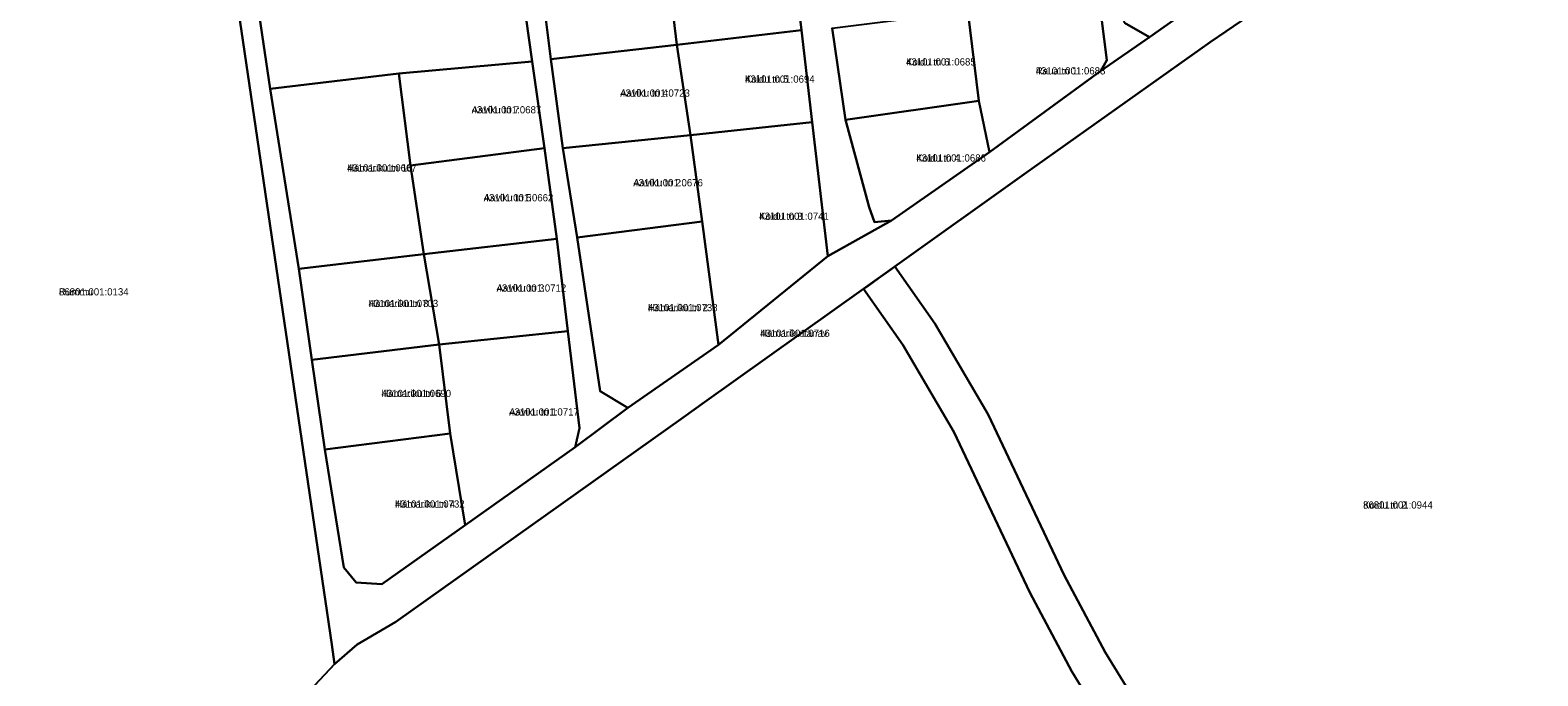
# Model space of a CAD drawing. Extents: x 484607 to 525396, y 6554521 to 6586559.
# Drawn here: x 510881.4 to 511195.3, y 6566189 to 6566323.4 of the extents above; entities that cross this region are included whole.
import ezdxf

# ---------------------------------------------------------------- set-up
doc = ezdxf.new("R2010")
doc.units = 0
for name, color, linetype in [('L_AADRESS', 7, 'Continuous'), ('PIIR', 7, 'Continuous'), ('TUNNUS', 7, 'Continuous')]:
    doc.layers.add(name, color=color, linetype=linetype)

msp = doc.modelspace()

# ---------------------------------------------------------------- linework, layer by layer
at = {"layer": 'PIIR'}
for points in [[(510798.29, 6566881.46), (510841.06, 6566895.36), (510898.65, 6566504.69), (510899.62, 6566498.05), (510944.17, 6566195.55), (510944.78, 6566191.44), (510919.04, 6566163.98), (510920.5, 6566161.21), (510972.39, 6566062.69), (510956.12, 6566056.16), (510964.27, 6566035.84), (510980.57, 6566010.49), (510903.8, 6565981.76), (510875.33, 6565935.94), (510855.65, 6566095.24), (510855.17, 6566099.11), (510854.85, 6566103.1), (510794.21, 6566862.32), (510794.75, 6566868.66)], [(511167.15, 6566348.39), (511195.72, 6566369.66), (511229.31, 6566328.43), (511197.85, 6566289.25), (511235.29, 6566228.71), (511213.97, 6566194.63), (511250.38, 6566142.85), (511256.39, 6566114.86), (511216.4, 6566103.03), (511185.24, 6566094.86), (511173.08, 6566091.4), (511165.87, 6566097.92), (511159.18, 6566104.64), (511153.91, 6566112.9), (511145.54, 6566128.22), (511105.24, 6566193.93), (511096.69, 6566209.97), (511080.89, 6566243.45), (511069.79, 6566262.38), (511061.46, 6566274.23), (511088.35, 6566293.42), (511127.12, 6566320.93), (511162.99, 6566345.41)], [(511109.24, 6566324.92), (511105.7, 6566349.28), (511132.11, 6566353.48), (511134.64, 6566336.25), (511114.47, 6566321.95)], [(510989.77, 6566317.4), (510987.42, 6566336.34), (511013.75, 6566339.47), (511016.02, 6566320.36)], [(511016.02, 6566320.36), (511013.75, 6566339.47), (511039.81, 6566341.91), (511041.99, 6566323.42)], [(510931.35, 6566311.19), (510928.61, 6566330.04), (510955.38, 6566333.19), (510983.27, 6566335.71), (510985.9, 6566316.93), (510958.13, 6566314.42)], [(511078.92, 6566308.7), (511076.65, 6566327.41), (511103.93, 6566330.36), (511105.55, 6566317.2), (511104.3, 6566314.95), (511081.13, 6566298.06)], [(511051.14, 6566304.74), (511048.39, 6566323.85), (511076.65, 6566327.41), (511078.92, 6566308.7)], [(511018.89, 6566301.56), (511016.02, 6566320.36), (511041.99, 6566323.42), (511044.21, 6566304.3)], [(510992.33, 6566298.83), (510989.77, 6566317.4), (511016.02, 6566320.36), (511018.89, 6566301.56)], [(510937.35, 6566273.71), (510931.35, 6566311.19), (510958.13, 6566314.42), (510960.55, 6566295.27), (510963.38, 6566276.77)], [(510960.55, 6566295.27), (510958.13, 6566314.42), (510985.9, 6566316.93), (510988.47, 6566298.84)], [(511056.11, 6566286.56), (511051.14, 6566304.74), (511078.92, 6566308.7), (511081.13, 6566298.06), (511060.76, 6566283.78), (511057.23, 6566283.44)], [(510995.3, 6566280.28), (510992.33, 6566298.83), (511018.89, 6566301.56), (511021.33, 6566283.6)], [(511021.33, 6566283.6), (511018.89, 6566301.56), (511044.21, 6566304.3), (511047.49, 6566276.37), (511024.74, 6566257.95)], [(510963.38, 6566276.77), (510960.55, 6566295.27), (510988.47, 6566298.84), (510991.02, 6566279.99)], [(511000.08, 6566248.3), (510995.3, 6566280.28), (511021.33, 6566283.6), (511024.74, 6566257.95), (511005.86, 6566244.8)], [(510966.52, 6566258.01), (510963.38, 6566276.77), (510991.02, 6566279.99), (510993.33, 6566260.79)], [(510940.04, 6566254.8), (510937.35, 6566273.71), (510963.38, 6566276.77), (510966.52, 6566258.01)], [(511061.46, 6566274.23), (511069.79, 6566262.38), (511080.89, 6566243.45), (511096.69, 6566209.97), (511105.24, 6566193.93), (511145.54, 6566128.22), (511153.91, 6566112.9), (511159.18, 6566104.64), (511165.87, 6566097.92), (511173.08, 6566091.4), (511146.85, 6566083.95), (511137.36, 6566078.64), (511143.81, 6566090.33), (511149.17, 6566104.85), (511138.61, 6566124.21), (511098.29, 6566189.95), (511089.54, 6566206.38), (511073.75, 6566239.83), (511063.12, 6566257.94), (511054.94, 6566269.58)], [(510968.86, 6566239.46), (510966.52, 6566258.01), (510993.33, 6566260.79), (510995.74, 6566240.55), (510994.85, 6566236.62), (510971.97, 6566220.4)], [(510942.75, 6566236.11), (510940.04, 6566254.8), (510966.52, 6566258.01), (510968.86, 6566239.46)], [(510946.73, 6566211.55), (510942.75, 6566236.11), (510968.86, 6566239.46), (510971.97, 6566220.4), (510954.6, 6566208.14), (510949.25, 6566208.42)]]:
    msp.add_lwpolyline(points, close=True, dxfattribs=at)
for points in [[(511162.99, 6566345.41), (511127.12, 6566320.93), (511088.35, 6566293.42), (511061.46, 6566274.23), (511060.58, 6566273.6), (511057.98, 6566271.75), (511055.57, 6566270.03), (511054.94, 6566269.58), (511021.81, 6566246), (511017.33, 6566242.81), (510957.55, 6566200.27), (510949.5, 6566195.54), (510944.78, 6566191.44), (510944.17, 6566195.55), (510899.62, 6566498.05)], [(511048.39, 6566323.85), (511051.14, 6566304.74), (511056.11, 6566286.56), (511057.23, 6566283.44), (511060.76, 6566283.78), (511047.49, 6566276.37), (511044.21, 6566304.3), (511041.99, 6566323.42), (511039.81, 6566341.91)], [(510928.61, 6566330.04), (510931.35, 6566311.19), (510937.35, 6566273.71), (510940.04, 6566254.8), (510942.75, 6566236.11), (510946.73, 6566211.55), (510949.25, 6566208.42), (510954.6, 6566208.14), (510971.97, 6566220.4), (510994.85, 6566236.62), (511005.86, 6566244.8), (511024.74, 6566257.95), (511047.49, 6566276.37), (511060.76, 6566283.78), (511081.13, 6566298.06), (511104.3, 6566314.95), (511114.47, 6566321.95), (511134.64, 6566336.25)], [(510987.42, 6566336.34), (510989.77, 6566317.4), (510992.33, 6566298.83), (510995.3, 6566280.28), (511000.08, 6566248.3), (511005.86, 6566244.8), (510994.85, 6566236.62), (510995.74, 6566240.55), (510993.33, 6566260.79), (510991.02, 6566279.99), (510988.47, 6566298.84), (510985.9, 6566316.93), (510983.27, 6566335.71)], [(511109.24, 6566324.92), (511114.47, 6566321.95), (511104.3, 6566314.95), (511105.55, 6566317.2), (511103.93, 6566330.36)], [(510919.04, 6566163.98), (510944.78, 6566191.44), (510949.5, 6566195.54), (510957.55, 6566200.27), (511017.33, 6566242.81), (511021.81, 6566246), (511054.94, 6566269.58), (511063.12, 6566257.94), (511073.75, 6566239.83), (511089.54, 6566206.38), (511098.29, 6566189.95), (511138.61, 6566124.21)]]:
    msp.add_lwpolyline(points, dxfattribs=at)

# ---------------------------------------------------------------- texts
at = {"layer": 'L_AADRESS'}
for s, p in [('Koidu tn 6', (511063.77, 6566316.07)), ('Koidu tn 5', (511030.24, 6566312.49)), ('Raua tn 1', (511090.77, 6566314.21)), ('Aaviku tn 4', (511004.25, 6566309.59)), ('Aaviku tn 7', (510973.31, 6566306.1)), ('Hämariku tn 10', (510947.37, 6566294)), ('Koidu tn 4', (511065.9, 6566296.07)), ('Aaviku tn 2', (511006.97, 6566290.92)), ('Aaviku tn 5', (510975.83, 6566287.8)), ('Koidu tn 3', (511033.19, 6566283.95)), ('Aaviku tn 3', (510978.51, 6566269)), ('Rummu', (510887.39, 6566268.21)), ('Hämariku tn 8', (510951.85, 6566265.79)), ('Hämariku tn 2', (511010.02, 6566264.93)), ('Hämariku tänav', (511033.38, 6566259.59)), ('Hämariku tn 6', (510954.53, 6566247.06)), ('Aaviku tn 1', (510981.13, 6566243.21)), ('Hämariku tn 4', (510957.36, 6566224.04)), ('Koidu tn 2', (511158.93, 6566223.84))]:
    msp.add_text(s, height=1.5, dxfattribs=at).set_placement(p)
at = {"layer": 'TUNNUS'}
for s, p in [('43101:001:0685', (511063.77, 6566316.07)), ('43101:001:0694', (511030.24, 6566312.49)), ('43101:001:0688', (511090.77, 6566314.21)), ('43101:001:0723', (511004.25, 6566309.59)), ('43101:001:0687', (510973.31, 6566306.1)), ('43101:001:0667', (510947.37, 6566294)), ('43101:001:0686', (511065.9, 6566296.07)), ('43101:001:0676', (511006.97, 6566290.92)), ('43101:001:0662', (510975.83, 6566287.8)), ('43101:001:0741', (511033.19, 6566283.95)), ('43101:001:0712', (510978.51, 6566269)), ('86801:001:0134', (510887.39, 6566268.21)), ('43101:001:0703', (510951.85, 6566265.79)), ('43101:001:0738', (511010.02, 6566264.93)), ('43101:001:0716', (511033.38, 6566259.59)), ('43101:001:0690', (510954.53, 6566247.06)), ('43101:001:0717', (510981.13, 6566243.21)), ('43101:001:0732', (510957.36, 6566224.04)), ('86801:001:0944', (511158.93, 6566223.84))]:
    msp.add_text(s, height=1.5, dxfattribs=at).set_placement(p)

doc.saveas('drawing.dxf')
